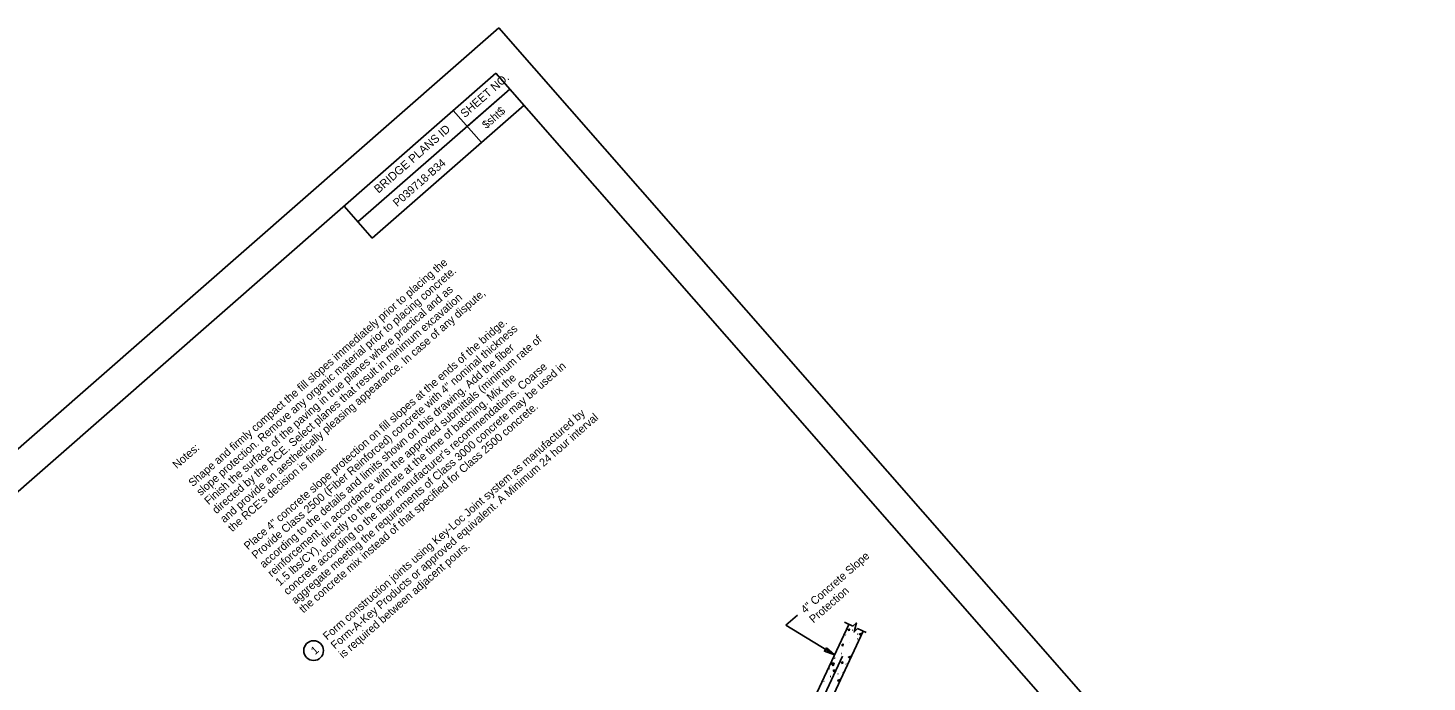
# Model space of a CAD drawing. Extents: x 1970965 to 1971298, y 796258 to 796581.
# Drawn here: x 1971122.8 to 1971297.6, y 796498.8 to 796580.6 of the extents above; entities that cross this region are included whole.
import ezdxf

# ---------------------------------------------------------------- set-up
doc = ezdxf.new("R2010")
doc.units = 0
for name, color, linetype in [('BR_AUTO DIMENSION', 7, 'Continuous'), ('BR_BORDER LINES', 7, 'Continuous'), ('BR_CENTER LINES', 7, 'Continuous'), ('BR_CONCRETE', 7, 'Continuous'), ('BR_REBAR', 7, 'Continuous'), ('BR_TABLE LINES', 7, 'Continuous'), ('BR_TEXT', 7, 'Continuous'), ('Level 31', 7, 'Continuous')]:
    doc.layers.add(name, color=color, linetype=linetype)

msp = doc.modelspace()

# ---------------------------------------------------------------- linework, layer by layer
at = {"layer": 'BR_AUTO DIMENSION'}
for p, q in [((1971217.49, 796505.88), (1971218.96, 796507.17)), ((1971223.56, 796502.17), (1971217.49, 796505.88))]:
    msp.add_line(p, q, dxfattribs=at)
msp.add_lwpolyline([(1971222.58, 796503.06), (1971223.56, 796502.17), (1971222.32, 796502.63)], close=True, dxfattribs=at)
at = {"layer": 'BR_BORDER LINES'}
for p, q in [((1971181.27, 796574.92), (1970978.66, 796397.47)), ((1971291.95, 796448.53), (1971181.27, 796574.92)), ((1971164.03, 796556.32), (1971183.01, 796572.93)), ((1971177.67, 796568.26), (1971183.01, 796572.93)), ((1971184.78, 796570.9), (1971165.81, 796554.29)), ((1971179.45, 796566.23), (1971175.94, 796570.25)), ((1971165.81, 796554.29), (1971162.3, 796558.3))]:
    msp.add_line(p, q, dxfattribs=at)
at = {"layer": 'BR_CENTER LINES'}
msp.add_lwpolyline([(1971226.46, 796505.49), (1971226.02, 796505.06), (1971226.32, 796506.19), (1971225.88, 796505.76)], dxfattribs=at)
at = {"layer": 'BR_CONCRETE'}
for p, q in [((1971215.93, 796485.9), (1971225.36, 796506)), ((1971218.46, 796486.59), (1971227.17, 796505.15))]:
    msp.add_line(p, q, dxfattribs=at)
at = {"layer": 'BR_REBAR'}
msp.add_line((1971217.28, 796486.42), (1971224.59, 796502.01), dxfattribs=at)
at = {"layer": 'BR_TABLE LINES'}
for p, q in [((1971225.88, 796505.76), (1971224.82, 796506.26)), ((1971227.53, 796504.98), (1971226.46, 796505.49))]:
    msp.add_line(p, q, dxfattribs=at)
at = {"layer": 'BR_TEXT'}
for p, q in [((1971224.98, 796504.65), (1971224.93, 796504.7)), ((1971225.77, 796505.26), (1971225.82, 796505.27)), ((1971226.44, 796504.19), (1971226.42, 796504.21)), ((1971226.44, 796504.76), (1971226.49, 796504.77)), ((1971224.41, 796502.37), (1971224.46, 796502.37)), ((1971225.5, 796503.77), (1971225.47, 796503.79)), ((1971222.95, 796500.39), (1971222.91, 796500.45)), ((1971223.62, 796501.75), (1971223.57, 796501.81)), ((1971225.02, 796501.03), (1971225, 796501.06)), ((1971222.26, 796498.86), (1971222.22, 796498.91)), ((1971223.05, 796499.47), (1971223.1, 796499.48)), ((1971223.97, 796499.83), (1971224.03, 796499.81)), ((1971224.67, 796499.99), (1971224.63, 796500.04))]:
    msp.add_line(p, q, dxfattribs=at)
for points in [[(1971225.39, 796505.18), (1971225.27, 796505.34), (1971225.43, 796505.42), (1971225.39, 796505.18)], [(1971226.93, 796504.63), (1971226.67, 796504.79), (1971227.02, 796504.91), (1971227.02, 796504.82)], [(1971224.62, 796503.29), (1971224.49, 796503.44), (1971224.65, 796503.53), (1971224.62, 796503.29)], [(1971223.39, 796500.81), (1971223.14, 796501.13), (1971223.51, 796501.13), (1971223.39, 796500.81)], [(1971224.57, 796501.08), (1971224.44, 796501.23), (1971224.6, 796501.31), (1971224.57, 796501.08)], [(1971225.57, 796501.73), (1971225.31, 796501.9), (1971225.66, 796502.02), (1971225.66, 796501.93)], [(1971223.53, 796500.07), (1971223.41, 796500.22), (1971223.57, 796500.3), (1971223.53, 796500.07)], [(1971224.21, 796498.84), (1971223.95, 796499), (1971224.3, 796499.12), (1971224.3, 796499.03)]]:
    msp.add_lwpolyline(points, dxfattribs=at)
msp.add_circle((1971158.49, 796502.72), 1.24, dxfattribs=at)
at = {"layer": 'Level 31'}
for p, q in [((1971181.65, 796580.56), (1970964.99, 796390.82)), ((1971297.6, 796448.16), (1971181.65, 796580.56))]:
    msp.add_line(p, q, dxfattribs=at)

# ---------------------------------------------------------------- texts
at = {"layer": 'BR_TEXT'}
for s, height, p in [('SHEET NO.', 1.04, (1971177.38, 796569.28)), ('$sht$', 1, (1971180.07, 796567.9)), ('BRIDGE PLANS ID', 1.04, (1971166.6, 796559.84)), ('P039718-B34', 1, (1971168.94, 796558.15)), ('Shape and firmly compact the fill slopes immediately prior to placing the', 0.9998, (1971143.39, 796523.15)), ('slope protection. Remove any organic material prior to placing concrete. ', 0.9998, (1971144.38, 796522.02)), ('Finish the surface of the paving in true planes where practical and as', 0.9998, (1971145.37, 796520.89)), ('and provide an aesthetically pleasing appearance. In case of any dispute, ', 0.9998, (1971147.34, 796518.63)), ('directed by the RCE. Select planes that result in minimum excavation', 0.9998, (1971146.35, 796519.76)), ('Place 4" concrete slope protection on fill slopes at the ends of the bridge. ', 0.9998, (1971150.31, 796515.25)), ('Provide Class 2500 (Fiber Reinforced) concrete with 4" nominal thickness ', 0.9998, (1971151.29, 796514.12)), ('according to the details and limits shown on this drawing. Add the fiber ', 0.9998, (1971152.28, 796512.99)), ('reinforcement, in accordance with the approved submittals (minimum rate of ', 0.9998, (1971153.27, 796511.86)), ('1.5 lbs/CY), directly to the concrete at the time of batching. Mix the ', 0.9998, (1971154.26, 796510.74)), ("concrete according to the fiber manufacturer's recommendations. Coarse ", 0.9998, (1971155.25, 796509.61)), ('aggregate meeting the requirements of Class 3000 concrete may be used in ', 0.9998, (1971156.23, 796508.48)), ('the concrete mix instead of that specified for Class 2500 concrete.', 0.9998, (1971157.22, 796507.35)), ('Form construction joints using Key-Loc Joint system as manufactured by ', 0.9998, (1971160.19, 796503.97)), ('Form-A-Key Products or approved equivalent. A Minimum 24 hour interval', 0.9998, (1971161.17, 796502.84)), ('Notes:', 1, (1971141.41, 796525.4)), ("the RCE's decision is final.", 0.9998, (1971148.33, 796517.51)), ('is required between adjacent pours.', 0.9998, (1971162.16, 796501.71)), ('4" Concrete Slope', 0.9997, (1971219.9, 796507.3)), ('Protection', 1, (1971220.95, 796506.1)), ('1', 1, (1971158.68, 796502.15))]:
    msp.add_text(s, height=height, rotation=41.212, dxfattribs=at).set_placement(p)

doc.saveas('drawing.dxf')
